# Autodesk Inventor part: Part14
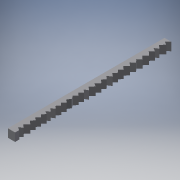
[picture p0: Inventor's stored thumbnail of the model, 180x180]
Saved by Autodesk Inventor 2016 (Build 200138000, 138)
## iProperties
Created: 2020-04
Part Number: Part14
Material: Generic
Document SubType Name: Modeling
Designer: merlin
Density: 1 g/cm^3
Appearance: Default
Author: merlin
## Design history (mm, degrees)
sketch "Sketch1"
  geometry: L1 (488.95, 179.387)-(488.95, 33.338); L2 (488.95, 33.338)-(482.6, 33.338); L3 (482.6, 33.338)-(485.775, 36.138); L4 (485.775, 36.138)-(482.6, 38.1); L5 (482.6, 38.1)-(485.775, 41.64); L6 (485.775, 41.64)-(482.6, 44.488); L7 (482.6, 44.488)-(485.775, 46.649); L8 (485.775, 46.649)-(482.6, 48.61); L9 (482.6, 48.61)-(485.314, 51.636); L10 (485.314, 51.636)-(481.814, 54.774); L11 (481.814, 54.774)-(484.883, 58.195); L12 (484.883, 58.195)-(481.814, 60.947); L13 (481.814, 60.947)-(484.863, 63.636); L14 (484.863, 63.636)-(482.182, 66.675); L15 (482.182, 66.675)-(485.322, 69.445); L16 (485.322, 69.445)-(482.35, 72.111); L17 (482.35, 72.111)-(485.314, 75.415); L18 (485.314, 75.415)-(482.35, 78.073); L19 (482.35, 78.073)-(484.883, 80.898); L20 (484.883, 80.898)-(482.35, 83.169); L21 (482.35, 83.169)-(484.883, 85.993); L22 (484.883, 85.993)-(481.814, 88.745); L23 (481.814, 88.745)-(485.314, 91.127); L24 (485.314, 91.127)-(482.35, 93.784); L25 (482.35, 93.784)-(484.883, 96.609); L26 (484.883, 96.609)-(481.814, 99.36); L27 (481.814, 99.36)-(484.883, 102.782); L28 (484.883, 102.782)-(481.814, 104.678); L29 (481.814, 104.678)-(484.883, 108.099); L30 (484.883, 108.099)-(481.814, 110.851); L31 (481.814, 110.851)-(484.883, 112.713); L32 (484.883, 112.713)-(482.35, 114.984); L33 (482.35, 114.984)-(484.883, 117.808); L34 (484.883, 117.808)-(482.35, 120.08); L35 (482.35, 120.08)-(484.883, 122.904); L36 (484.883, 122.904)-(482.942, 125.756); L37 (482.942, 125.756)-(484.883, 128.897); L38 (484.883, 128.897)-(482.35, 131.168); L39 (482.35, 131.168)-(484.883, 133.993); L40 (484.883, 133.993)-(482.35, 136.264); L41 (482.35, 136.264)-(484.883, 139.089); L42 (484.883, 139.089)-(482.35, 141.36); L43 (482.35, 141.36)-(485.314, 143.377); L44 (485.314, 143.377)-(482.35, 146.035); L45 (482.35, 146.035)-(485.314, 148.052); L46 (485.314, 148.052)-(482.35, 149.883); L47 (482.35, 149.883)-(484.883, 152.707); L48 (484.883, 152.707)-(482.35, 154.979); L49 (482.35, 154.979)-(484.883, 157.803); L50 (484.883, 157.803)-(482.35, 160.075); L51 (482.35, 160.075)-(484.883, 162.899); L52 (484.883, 162.899)-(481.814, 165.651); L53 (481.814, 165.651)-(484.883, 169.073); L54 (484.883, 169.073)-(482.182, 171.495); L55 (482.182, 171.495)-(484.913, 173.904); L56 (484.913, 173.904)-(482.182, 175.592); L57 (482.182, 175.592)-(482.182, 179.387); L58 (482.182, 179.387)-(488.95, 179.387); 1 further point
  constraints: 116 end point, 38 perpendicular, 13 parallel, 1 vertical
extrude "Extrusion1" new body sketch "Sketch1" distance "d0" = 7.62; taper "d1" = 0 deg
body "Solid1"
